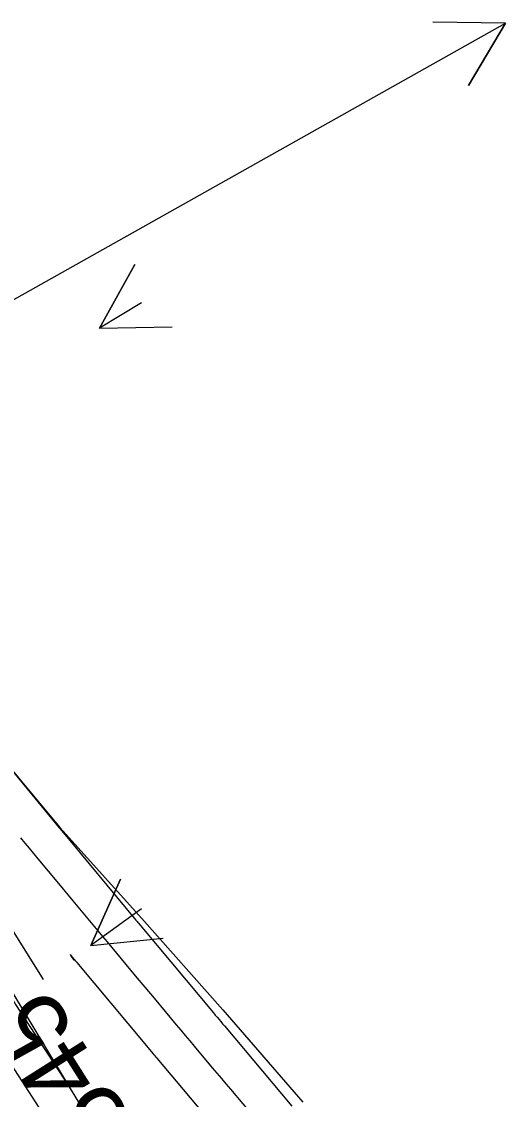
# Model space of a CAD drawing. Extents: x 954385 to 988206, y 1868364 to 1924553.
# Drawn here: x 957697.2 to 957737.1, y 1920153.2 to 1920242.1 of the extents above; entities that cross this region are included whole.
import ezdxf

# ---------------------------------------------------------------- set-up
doc = ezdxf.new("R2010")
doc.units = 0
for name, color, linetype in [('16', 7, 'Continuous'), ('24', 7, 'Continuous'), ('26', 7, 'Continuous'), ('5', 7, 'Continuous'), ('6', 7, 'Continuous'), ('7', 7, 'Continuous')]:
    doc.layers.add(name, color=color, linetype=linetype)

msp = doc.modelspace()

# ---------------------------------------------------------------- linework, layer by layer
at = {"layer": '16'}
for points in [[(957642.475, 1920245.119), (957647.904, 1920236.718), (957650.092, 1920233.249), (957653.344, 1920228.325), (957658.665, 1920219.852), (957664.238, 1920211.548), (957669.658, 1920203.141), (957675.294, 1920194.881), (957680.805, 1920186.536), (957686.502, 1920178.317), (957690.062, 1920172.865), (957691.817, 1920169.839), (957696.948, 1920161.236), (957702.103, 1920152.651)], [(957672.968, 1920198.29), (957674.612, 1920195.665), (957674.887, 1920195.228), (957675.161, 1920194.791), (957675.436, 1920194.354), (957675.712, 1920193.918), (957680.487, 1920186.357), (957680.511, 1920186.319), (957680.586, 1920186.201), (957685.024, 1920179.228), (957685.449, 1920178.56), (957685.875, 1920177.893), (957686.302, 1920177.225), (957686.729, 1920176.558), (957689.363, 1920172.446), (957689.399, 1920172.39), (957689.411, 1920172.371), (957691.265, 1920169.489), (957691.286, 1920169.456), (957696.692, 1920161.094), (957696.719, 1920161.052), (957701.051, 1920154.402)], [(957699.54, 1920151.226), (957694.374, 1920159.155)]]:
    msp.add_lwpolyline(points, dxfattribs=at)
at = {"layer": '24'}
msp.add_lwpolyline([(957645.505, 1920247.168), (957651.24, 1920238.975), (957657.104, 1920230.868), (957663.303, 1920222.989), (957669.266, 1920214.949), (957671.938, 1920211.601), (957675.531, 1920207.114), (957681.545, 1920199.11), (957687.849, 1920191.301), (957693.938, 1920183.347), (957700.39, 1920175.638), (957707.155, 1920168.141), (957713.84, 1920160.59), (957720.434, 1920152.977)], dxfattribs=at)
at = {"layer": '26'}
for points in [[(957607.131, 1920168.928), (957737.148, 1920242.007), (957734.089, 1920236.845), (957737.148, 1920242.007), (957731.149, 1920242.076)], [(957707.131, 1920218.928), (957703.657, 1920216.842), (957706.568, 1920222.089), (957703.657, 1920216.842), (957709.656, 1920216.945)], [(957707.131, 1920168.928), (957702.945, 1920165.894), (957705.392, 1920171.373), (957702.945, 1920165.894), (957708.913, 1920166.515)]]:
    msp.add_lwpolyline(points, dxfattribs=at)
at = {"layer": '6'}
msp.add_lwpolyline([(957696.171, 1920180.679), (957700.334, 1920175.626), (957700.361, 1920175.593), (957700.415, 1920175.529), (957706.66, 1920168.003), (957706.712, 1920167.94), (957706.765, 1920167.877), (957706.818, 1920167.814), (957706.87, 1920167.751), (957707.292, 1920167.247), (957713.061, 1920160.344), (957713.136, 1920160.254), (957713.211, 1920160.165), (957713.287, 1920160.075), (957713.362, 1920159.986), (957713.663, 1920159.628), (957713.814, 1920159.449), (957713.964, 1920159.27), (957719.523, 1920152.665)], dxfattribs=at)
at = {"layer": '7'}
for points in [[(957697.151, 1920174.794), (957697.508, 1920174.362), (957697.864, 1920173.929), (957698.222, 1920173.498), (957698.579, 1920173.066), (957700.264, 1920171.034), (957700.665, 1920170.552), (957701.065, 1920170.07), (957701.465, 1920169.587), (957701.865, 1920169.105), (957703.506, 1920167.127), (957703.893, 1920166.662), (957704.28, 1920166.196), (957704.668, 1920165.731), (957705.056, 1920165.267), (957706.609, 1920163.408), (957707.386, 1920162.479), (957708.162, 1920161.55), (957709.983, 1920159.372), (957710.355, 1920158.928), (957710.727, 1920158.484), (957711.099, 1920158.041), (957711.472, 1920157.598), (957712.963, 1920155.826), (957713.336, 1920155.383), (957713.709, 1920154.94), (957714.082, 1920154.497), (957714.455, 1920154.054), (957716.497, 1920151.627)], [(957699.025, 1920163.094), (957694.387, 1920170.491)], [(957713.327, 1920150.761), (957708.405, 1920156.607), (957708.323, 1920156.705), (957708.241, 1920156.802), (957708.159, 1920156.9), (957708.077, 1920156.998), (957707.422, 1920157.782), (957701.811, 1920164.494), (957701.778, 1920164.534), (957701.712, 1920164.614), (957701.323, 1920165.083), (957701.27, 1920165.143), (957701.249, 1920165.16), (957701.259, 1920165.135), (957701.3, 1920165.066), (957701.538, 1920164.686)]]:
    msp.add_lwpolyline(points, dxfattribs=at)

# ---------------------------------------------------------------- texts
at = {"layer": '5'}
msp.add_text('545', height=6, rotation=122.35719, dxfattribs=at).set_placement((957706.501, 1920151.342))

doc.saveas('drawing.dxf')
